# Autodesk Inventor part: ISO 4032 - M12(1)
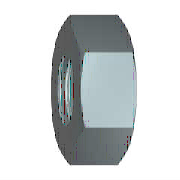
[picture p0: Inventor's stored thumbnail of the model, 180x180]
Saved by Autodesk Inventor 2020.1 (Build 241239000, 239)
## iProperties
Created: 2019-01
Part Number: ISO 4032 - M12(1)
Material: Edelstahl, 440C
Description: Sechskantmutter
Document SubType Name: Modeling
Standard: ISO 4032
Designer: lutzd
Standards Organization: DIN
Language: de-DE
Size Designation: M12
Categories: <MemberInstance><Categories><Category DisplayName="Verbindungselemente" InternalName="e4da775c-781d-43d5-af7c-5136215cf5a6" Mnemonic="FSTN"><Category DisplayNam
Mass: 16.2537 g
Surface Area: 13.2759 cm^2
Volume: 2.09725 cm^3
Density: 7.75 g/cm^3
Appearance: Halbpoliert
IsCustomPart: 0
Author: lutzd
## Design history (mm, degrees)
workaxis "Work Axis1"
workplane "Work Plane1"
sketch "Skizze1"
  geometry: L1 (-10.392, 0)-(-5.196, 9); L2 (-5.196, 9)-(5.196, 9); L3 (5.196, 9)-(10.392, 0); L4 (10.392, 0)-(5.196, -9); L5 (5.196, -9)-(-5.196, -9); L6 (-5.196, -9)-(-10.392, 0); 2 further points
  constraints: 12 end point, 1 coincident, 1 horizontal, 11 other
  dimensions: "d0" = 20.78461 distance of L3.end L1.start (= 1.1547 x SW)
extrude "Körper" new body sketch "Skizze1" distance "d1" = 10.8 (= KOH); taper "d2" = 0 deg
sketch "Skizze2"
  geometry: L1 (0, 5.196)-(0, 10.392) reference; L2 (0, 10.392)-(10.8, 10.392) reference; L3 (10.8, 5.196)-(10.8, 10.392) reference; L4 (-2.16, 0)-(12.96, 0) reference; L5 (1.208, 10.392)-(0, 8.3); L6 (9.592, 10.392)-(10.8, 8.3)
  constraints: 4 end point, 4 point on line
  dimensions: "d3" = 30 deg angle of L1 L5 (= ANG1); "d4" = 30 deg angle of L3 L6 (= ANG2); "d5" = 16.6 diameter of L5.end L4 (= SW0); "d6" = 16.6 diameter of L6.end L4 (= SW01)
revolve "Fase1" stored, may be unused: angle "d7" = 90 deg
sketch "Skizze3"
  geometry: 4 further points
  constraints: 1 coincident, 1 other
hole "Gewinde" sketch "Skizze3" diameter "d25" = 10.106; stored, may be unused: countersink angle "d29" = 82 deg, drill point angle "d31" = 118 deg; dims "d26" = 6, "d27" = 4, "d28" = 2, "d30" = 8
body "Solid1"
chamfer "Fase2" distance "d8" = 0.94722 (= -0.5 x GD1 + 0.5 x NND); stored, may be unused: angle "d9" = 30 deg, second distance "d40" = 0.94722 (= -0.5 x GD1 + 0.5 x NND)
chamfer "Fase3" distance "d10" = 0.94722 (= -0.5 x GD1 + 0.5 x NND); stored, may be unused: angle "d11" = 30 deg, second distance "d41" = 0.94722 (= -0.5 x GD1 + 0.5 x NND)
other parameters: "ANG1" = 30 deg [user parameter; used in 1 equation term], "ANG2" = 30 deg [user parameter; used in 1 equation term], "NND" = 12 [user parameter; used in 4 equation terms], "KOH" = 10.8 [user parameter; used in 1 equation term], "SW" = 18 [user parameter; used in 2 equation terms], "SW0" = 16.6 [user parameter; used in 1 equation term], "SW01" = 16.6 [user parameter; used in 1 equation term], "GD1" = 10.10557 (computed from THREADDIA, PTC, TOA) [user parameter; used in 4 equation terms], "d13" = 0, "d14" = 0, "d39" = 0, "d42" = 0, "GUL" = 0.94722 (= 0.541266 x PTC) [user parameter], "TPU" = 5.71429 (computed from PTC) [user parameter], "THREADDIA" = 12 [user parameter; used in 1 equation term], "TOA" = 30 deg [user parameter; used in 1 equation term], "PTC" = 1.75 [user parameter; used in 4 equation terms], "E0" = 20.79 (= 1.155 x SW) [user parameter], "GAL" = 0.94722 (= 0.541266 x PTC) [user parameter]
